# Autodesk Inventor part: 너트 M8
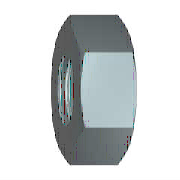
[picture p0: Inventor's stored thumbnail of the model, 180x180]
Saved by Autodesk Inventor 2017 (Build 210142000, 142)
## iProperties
IsCustomPart: 1
Created: 2012-02
Part Number: 너트 M8
Material: 강철, 연강
Description: 6각 너트 및 6각 가는 너트
Document SubType Name: Modeling
Standard: KS B 1012
Designer: mduedu
Standards Organization: KS
Language: ko-KR
Size Designation: M 8
Categories: <MemberInstance><Categories><Category DisplayName="조임쇠" InternalName="e4da775c-781d-43d5-af7c-5136215cf5a6" Mnemonic="FSTN"><Category DisplayName="너트" InternalN
Density: 1 g/cm^3
Appearance: 강철
Author: mduedu
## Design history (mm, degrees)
sketch "스케치1"
  geometry: L1 (-7.506, 0)-(-3.753, 6.5); L2 (-3.753, 6.5)-(3.753, 6.5); L3 (3.753, 6.5)-(7.506, 0); L4 (7.506, 0)-(3.753, -6.5); L5 (3.753, -6.5)-(-3.753, -6.5); L6 (-3.753, -6.5)-(-7.506, 0); 2 further points
  constraints: 12 end point, 1 coincident, 1 horizontal, 11 other
  dimensions: "d0" = 15.01111 distance of L3.end L1.start (= 1.1547 x SW)
extrude "본체" new body sketch "스케치1" distance "d1" = 5 (= KOH); taper "d2" = 0 deg
sketch "스케치2"
  geometry: L1 (0, 3.753)-(0, 7.506) reference; L2 (0, 7.506)-(5, 7.506) reference; L3 (5, 3.753)-(5, 7.506) reference; L4 (-1, 0)-(6, 0) reference; L5 (0.581, 7.506)-(0, 6.5); L6 (4.419, 7.506)-(5, 6.5)
  constraints: 4 end point, 4 point on line
  dimensions: "d3" = 30 deg angle of L1 L5 (= ANG1); "d4" = 30 deg angle of L3 L6 (= ANG2); "d5" = 13 diameter of L5.end L4 (= SW0); "d6" = 13 diameter of L6.end L4 (= SW01)
revolve "모따기1" sketch "스케치2" stored, may be unused: angle "d7" = 90 deg
sketch "스케치3"
  geometry: A1 r 6.5 centre (0, 0) between (-3.25, -5.629) and (3.25, -5.629) reference; 1 further point
  constraints: 1 coincident
hole "스레드" sketch "스케치3" at (0, 0) diameter "d25" = 6.647; stored, may be unused: countersink angle "d29" = 82 deg, drill point angle "d31" = 118 deg; dims "d26" = 6, "d27" = 4, "d28" = 2, "d30" = 8
workaxis "Work Axis1"
workplane "Work Plane1"
body "Solid1"
chamfer "모따기2" distance "d8" = 0.67658 (= -0.5 x GD1 + 0.5 x NND); stored, may be unused: angle "d9" = 30 deg, second distance "d40" = 0.67658 (= -0.5 x GD1 + 0.5 x NND)
chamfer "모따기3" distance "d10" = 0.67658 (= -0.5 x GD1 + 0.5 x NND); stored, may be unused: angle "d11" = 30 deg, second distance "d41" = 0.67658 (= -0.5 x GD1 + 0.5 x NND)
other parameters: "ANG1" = 30 deg [user parameter; used in 1 equation term], "ANG2" = 30 deg [user parameter; used in 1 equation term], "NND" = 8 [user parameter; used in 4 equation terms], "KOH" = 5 [user parameter; used in 1 equation term], "SW" = 13 [user parameter; used in 4 equation terms], "SW0" = 13 (= SW) [user parameter; used in 1 equation term], "SW01" = 13 (= SW) [user parameter; used in 1 equation term], "GD1" = 6.64684 (computed from THREADDIA, PTC, TOA) [user parameter; used in 4 equation terms], "d13" = 0, "d14" = 0, "d39" = 0, "d42" = 0, "GUL" = 0.67658 (= 0.541266 x PTC) [user parameter], "TPU" = 8 (computed from PTC) [user parameter], "THREADDIA" = 8 [user parameter; used in 1 equation term], "TOA" = 30 deg [user parameter; used in 1 equation term], "PTC" = 1.25 [user parameter; used in 4 equation terms], "E0" = 15.015 (= 1.155 x SW) [user parameter], "GAL" = 0.67658 (= 0.541266 x PTC) [user parameter]
